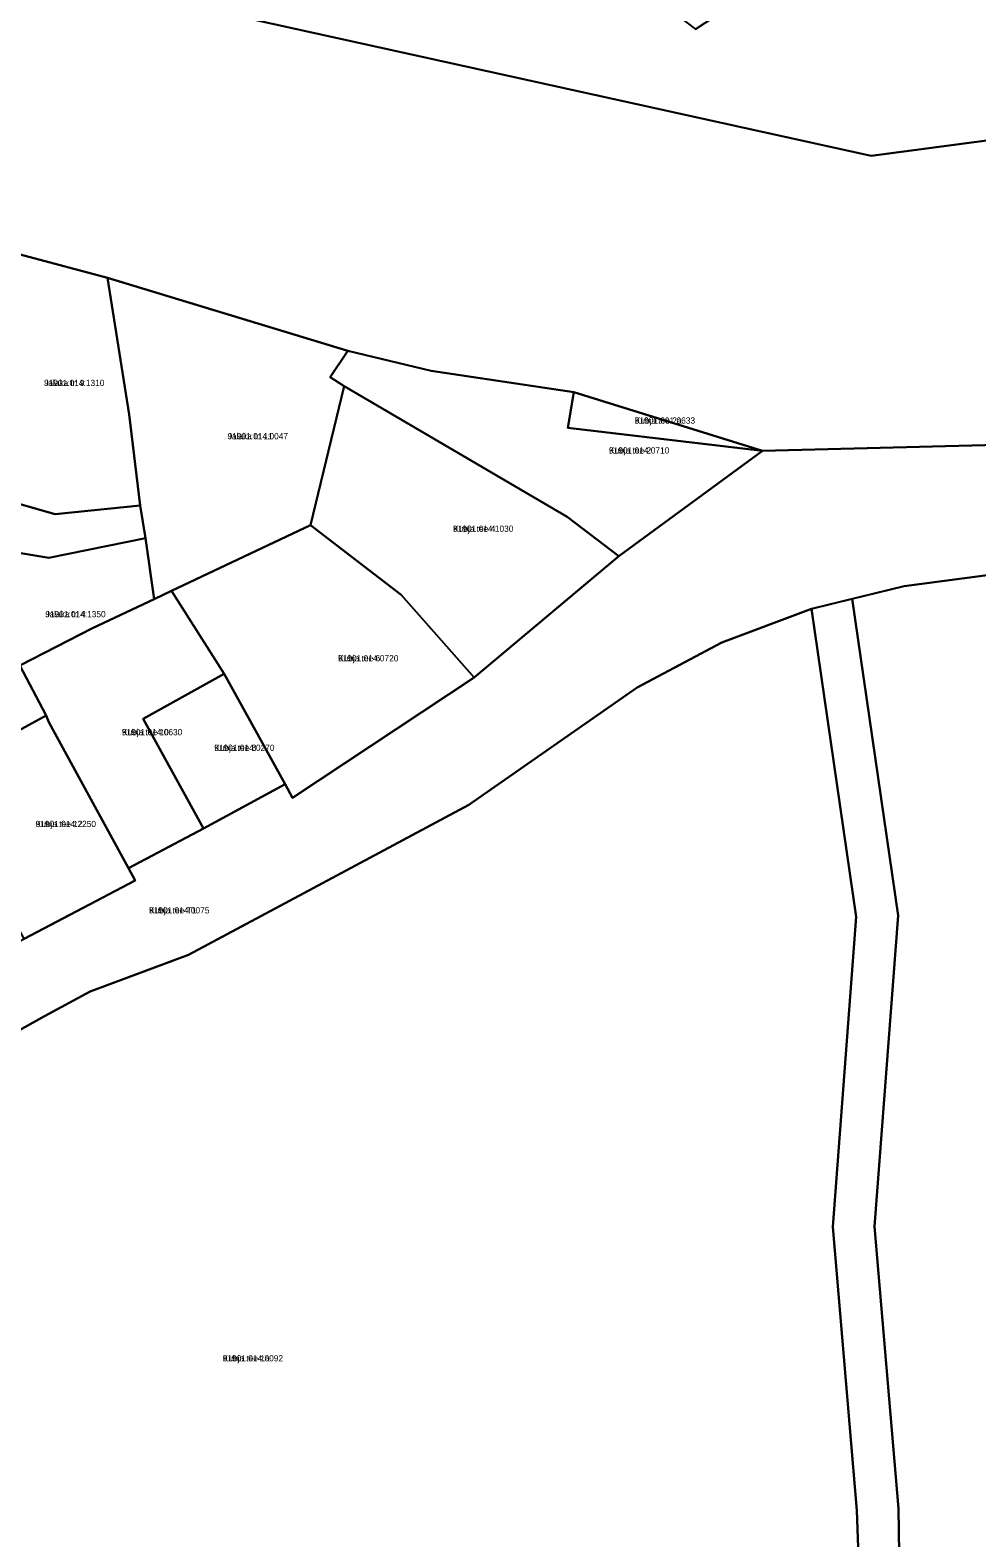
# Model space of a CAD drawing. Extents: x 675810 to 681273, y 6411190 to 6417565.
# Drawn here: x 678603.7 to 678831.3, y 6413180.1 to 6413542.7 of the extents above; entities that cross this region are included whole.
import ezdxf

# ---------------------------------------------------------------- set-up
doc = ezdxf.new("R2010")
doc.units = 0
for name, color, linetype in [('L_AADRESS', 7, 'Continuous'), ('PIIR', 7, 'Continuous'), ('TUNNUS', 7, 'Continuous')]:
    doc.layers.add(name, color=color, linetype=linetype)

msp = doc.modelspace()

# ---------------------------------------------------------------- linework, layer by layer
at = {"layer": 'PIIR'}
for points in [[(678665.74, 6413606.8), (678695.3, 6413600.11), (678714.53, 6413595.62), (678719.84, 6413576.34), (678763.72, 6413543), (678800.26, 6413567.02), (678800.48, 6413554.63), (678847.87, 6413557.53), (678857.44, 6413533.51), (678880.23, 6413542.83), (678888.05, 6413523.44), (678805.9, 6413512.49), (678631.5, 6413551.06), (678639.57, 6413556.01), (678656.18, 6413588.23)], [(678593.96, 6413469.73), (678601.35, 6413488.77), (678622.33, 6413483.15), (678627.53, 6413450.29), (678630.17, 6413428.46), (678609.77, 6413426.33), (678584.01, 6413433.67)], [(678622.33, 6413483.15), (678680.14, 6413465.61), (678675.83, 6413459.32), (678679.22, 6413457.12), (678671.14, 6413423.71), (678637.71, 6413407.92), (678633.57, 6413405.93), (678631.49, 6413420.57), (678630.17, 6413428.46), (678627.53, 6413450.29)], [(678680.14, 6413465.61), (678700.16, 6413460.78), (678734.44, 6413455.67), (678733.01, 6413447.1), (678779.84, 6413441.57), (678745.28, 6413416.24), (678732.85, 6413425.68), (678679.22, 6413457.12), (678675.83, 6413459.32)], [(678526.6, 6413450.17), (678533.98, 6413455.3), (678540, 6413446.17), (678561.79, 6413440), (678584.01, 6413433.67), (678609.77, 6413426.33), (678630.17, 6413428.46), (678631.49, 6413420.57), (678608.2, 6413415.87), (678595.07, 6413418.02), (678559.91, 6413424.12), (678547.61, 6413426.26), (678533.88, 6413437.98)], [(678710.5, 6413387.05), (678692.95, 6413406.94), (678671.14, 6413423.71), (678679.22, 6413457.12), (678732.85, 6413425.68), (678745.28, 6413416.24)], [(678734.44, 6413455.67), (678779.84, 6413441.57), (678733.01, 6413447.1)], [(678692.95, 6413406.94), (678710.5, 6413387.05), (678666.81, 6413358.15), (678665.04, 6413361.36), (678650.35, 6413387.95), (678637.71, 6413407.92), (678671.14, 6413423.71)], [(678585.46, 6413383.81), (678595.07, 6413418.02), (678608.2, 6413415.87), (678631.49, 6413420.57), (678633.57, 6413405.93), (678618.75, 6413398.88), (678601.3, 6413389.95), (678586.02, 6413382.5)], [(678627.38, 6413341.21), (678613.08, 6413367.48), (678608.23, 6413376.32), (678607.62, 6413377.91), (678601.3, 6413389.95), (678618.75, 6413398.88), (678633.57, 6413405.93), (678637.71, 6413407.92), (678650.35, 6413387.95), (678630.94, 6413377.1), (678645.38, 6413350.73)], [(678545.52, 6413358.41), (678537.34, 6413358.32), (678545.11, 6413363.44), (678557.92, 6413369.3), (678573.76, 6413376.53), (678586.02, 6413382.5), (678601.3, 6413389.95), (678607.62, 6413377.91), (678581.15, 6413363.52), (678583.38, 6413358.97), (678555.83, 6413345.79)], [(678665.04, 6413361.36), (678645.38, 6413350.73), (678630.94, 6413377.1), (678650.35, 6413387.95)], [(678583.38, 6413358.97), (678581.15, 6413363.52), (678607.62, 6413377.91), (678608.23, 6413376.32), (678613.08, 6413367.48), (678627.38, 6413341.21), (678628.99, 6413338.24), (678602.33, 6413324.19)]]:
    msp.add_lwpolyline(points, close=True, dxfattribs=at)
for points in [[(678858.38, 6413443.59), (678779.84, 6413441.57), (678734.44, 6413455.67), (678700.16, 6413460.78), (678680.14, 6413465.61), (678622.33, 6413483.15), (678601.35, 6413488.77), (678573.26, 6413496.02), (678477.82, 6413522.85), (678293.96, 6413581.95)], [(678631.5, 6413551.06), (678805.9, 6413512.49), (678888.05, 6413523.44), (678904.2, 6413483.51), (678924.74, 6413485.78), (678914.04, 6413512.86), (678965.52, 6413517.11), (678963.55, 6413537.52), (678984.06, 6413538.75), (678982.22, 6413567.37)], [(678435.46, 6413132.45), (678468.34, 6413187.35), (678498.35, 6413238.03), (678502.03, 6413243.37), (678495.22, 6413248.88), (678511.35, 6413266), (678545.3, 6413296.17), (678547.71, 6413293.36), (678557.93, 6413300.6), (678602.33, 6413324.19), (678628.99, 6413338.24), (678627.38, 6413341.21), (678645.38, 6413350.73), (678665.04, 6413361.36), (678666.81, 6413358.15), (678710.5, 6413387.05), (678745.28, 6413416.24), (678779.84, 6413441.57), (678858.38, 6413443.59)], [(678837.49, 6413412.16), (678813.86, 6413408.99), (678791.56, 6413403.6), (678770.01, 6413395.44), (678749.7, 6413384.68), (678709.22, 6413356.39), (678663.86, 6413332.17), (678641.85, 6413320.32), (678618.17, 6413311.55), (678607.18, 6413305.63), (678574.88, 6413287.6), (678555.09, 6413274.2), (678537.66, 6413258.57), (678522.47, 6413240.32), (678515.7, 6413230.29), (678508.92, 6413220.26), (678502.59, 6413209.66), (678496.26, 6413199.06), (678490.99, 6413179.42)], [(678779.57, 6412808.96), (678788.22, 6412862.99), (678805.85, 6412948.1), (678819.14, 6413056.64), (678815.99, 6413089.3), (678812.98, 6413154.83), (678812.47, 6413187.23), (678806.72, 6413255.01), (678812.39, 6413329.81), (678801.32, 6413405.96), (678813.86, 6413408.99), (678837.49, 6413412.16)], [(678490.99, 6413179.42), (678496.26, 6413199.06), (678502.59, 6413209.66), (678508.92, 6413220.26), (678515.7, 6413230.29), (678522.47, 6413240.32), (678537.66, 6413258.57), (678555.09, 6413274.2), (678574.88, 6413287.6), (678607.18, 6413305.63), (678618.17, 6413311.55), (678641.85, 6413320.32), (678663.86, 6413332.17), (678709.22, 6413356.39), (678749.7, 6413384.68), (678770.01, 6413395.44), (678791.56, 6413403.6), (678802.33, 6413329.46), (678796.69, 6413254.97), (678802.47, 6413186.73), (678806.01, 6413088.59)], [(678752.54, 6412739.48), (678778.38, 6412864.78), (678795.98, 6412949.73), (678809.08, 6413056.77), (678806.01, 6413088.59), (678802.47, 6413186.73), (678796.69, 6413254.97), (678802.33, 6413329.46), (678791.56, 6413403.6), (678801.32, 6413405.96), (678812.39, 6413329.81), (678806.72, 6413255.01), (678812.47, 6413187.23), (678812.98, 6413154.83), (678815.99, 6413089.3), (678819.14, 6413056.64), (678805.85, 6412948.1), (678788.22, 6412862.99), (678779.57, 6412808.96)]]:
    msp.add_lwpolyline(points, dxfattribs=at)

# ---------------------------------------------------------------- texts
at = {"layer": 'L_AADRESS'}
for s, p in [('Jalaka tn 9', (678607.09, 6413457.16)), ('Kubja tee 2a', (678749.1, 6413448.11)), ('Jalaka tn 11', (678651.23, 6413444.34)), ('Kubja tee 2', (678742.9, 6413440.92)), ('Kubja tee 4', (678705.42, 6413422.09)), ('Jalaka tn 4', (678607.39, 6413401.54)), ('Kubja tee 6', (678677.77, 6413390.93)), ('Kubja tee 10', (678625.82, 6413373.16)), ('Kubja tee 8', (678647.99, 6413369.39)), ('Kubja tee 12', (678605.07, 6413351.08)), ('Kubja tee T1', (678632.33, 6413330.31)), ('Kubja tee 1a', (678650.04, 6413222.57))]:
    msp.add_text(s, height=1.5, dxfattribs=at).set_placement(p)
at = {"layer": 'TUNNUS'}
for s, p in [('91901:014:1310', (678607.09, 6413457.16)), ('91901:001:0633', (678749.1, 6413448.11)), ('91901:014:0047', (678651.23, 6413444.34)), ('91901:014:0710', (678742.9, 6413440.92)), ('91901:014:1030', (678705.42, 6413422.09)), ('91901:014:1350', (678607.39, 6413401.54)), ('91901:014:0720', (678677.77, 6413390.93)), ('91901:014:0630', (678625.82, 6413373.16)), ('91901:014:0270', (678647.99, 6413369.39)), ('91901:014:2250', (678605.07, 6413351.08)), ('91901:014:0075', (678632.33, 6413330.31)), ('91901:014:0092', (678650.04, 6413222.57))]:
    msp.add_text(s, height=1.5, dxfattribs=at).set_placement(p)

doc.saveas('drawing.dxf')
